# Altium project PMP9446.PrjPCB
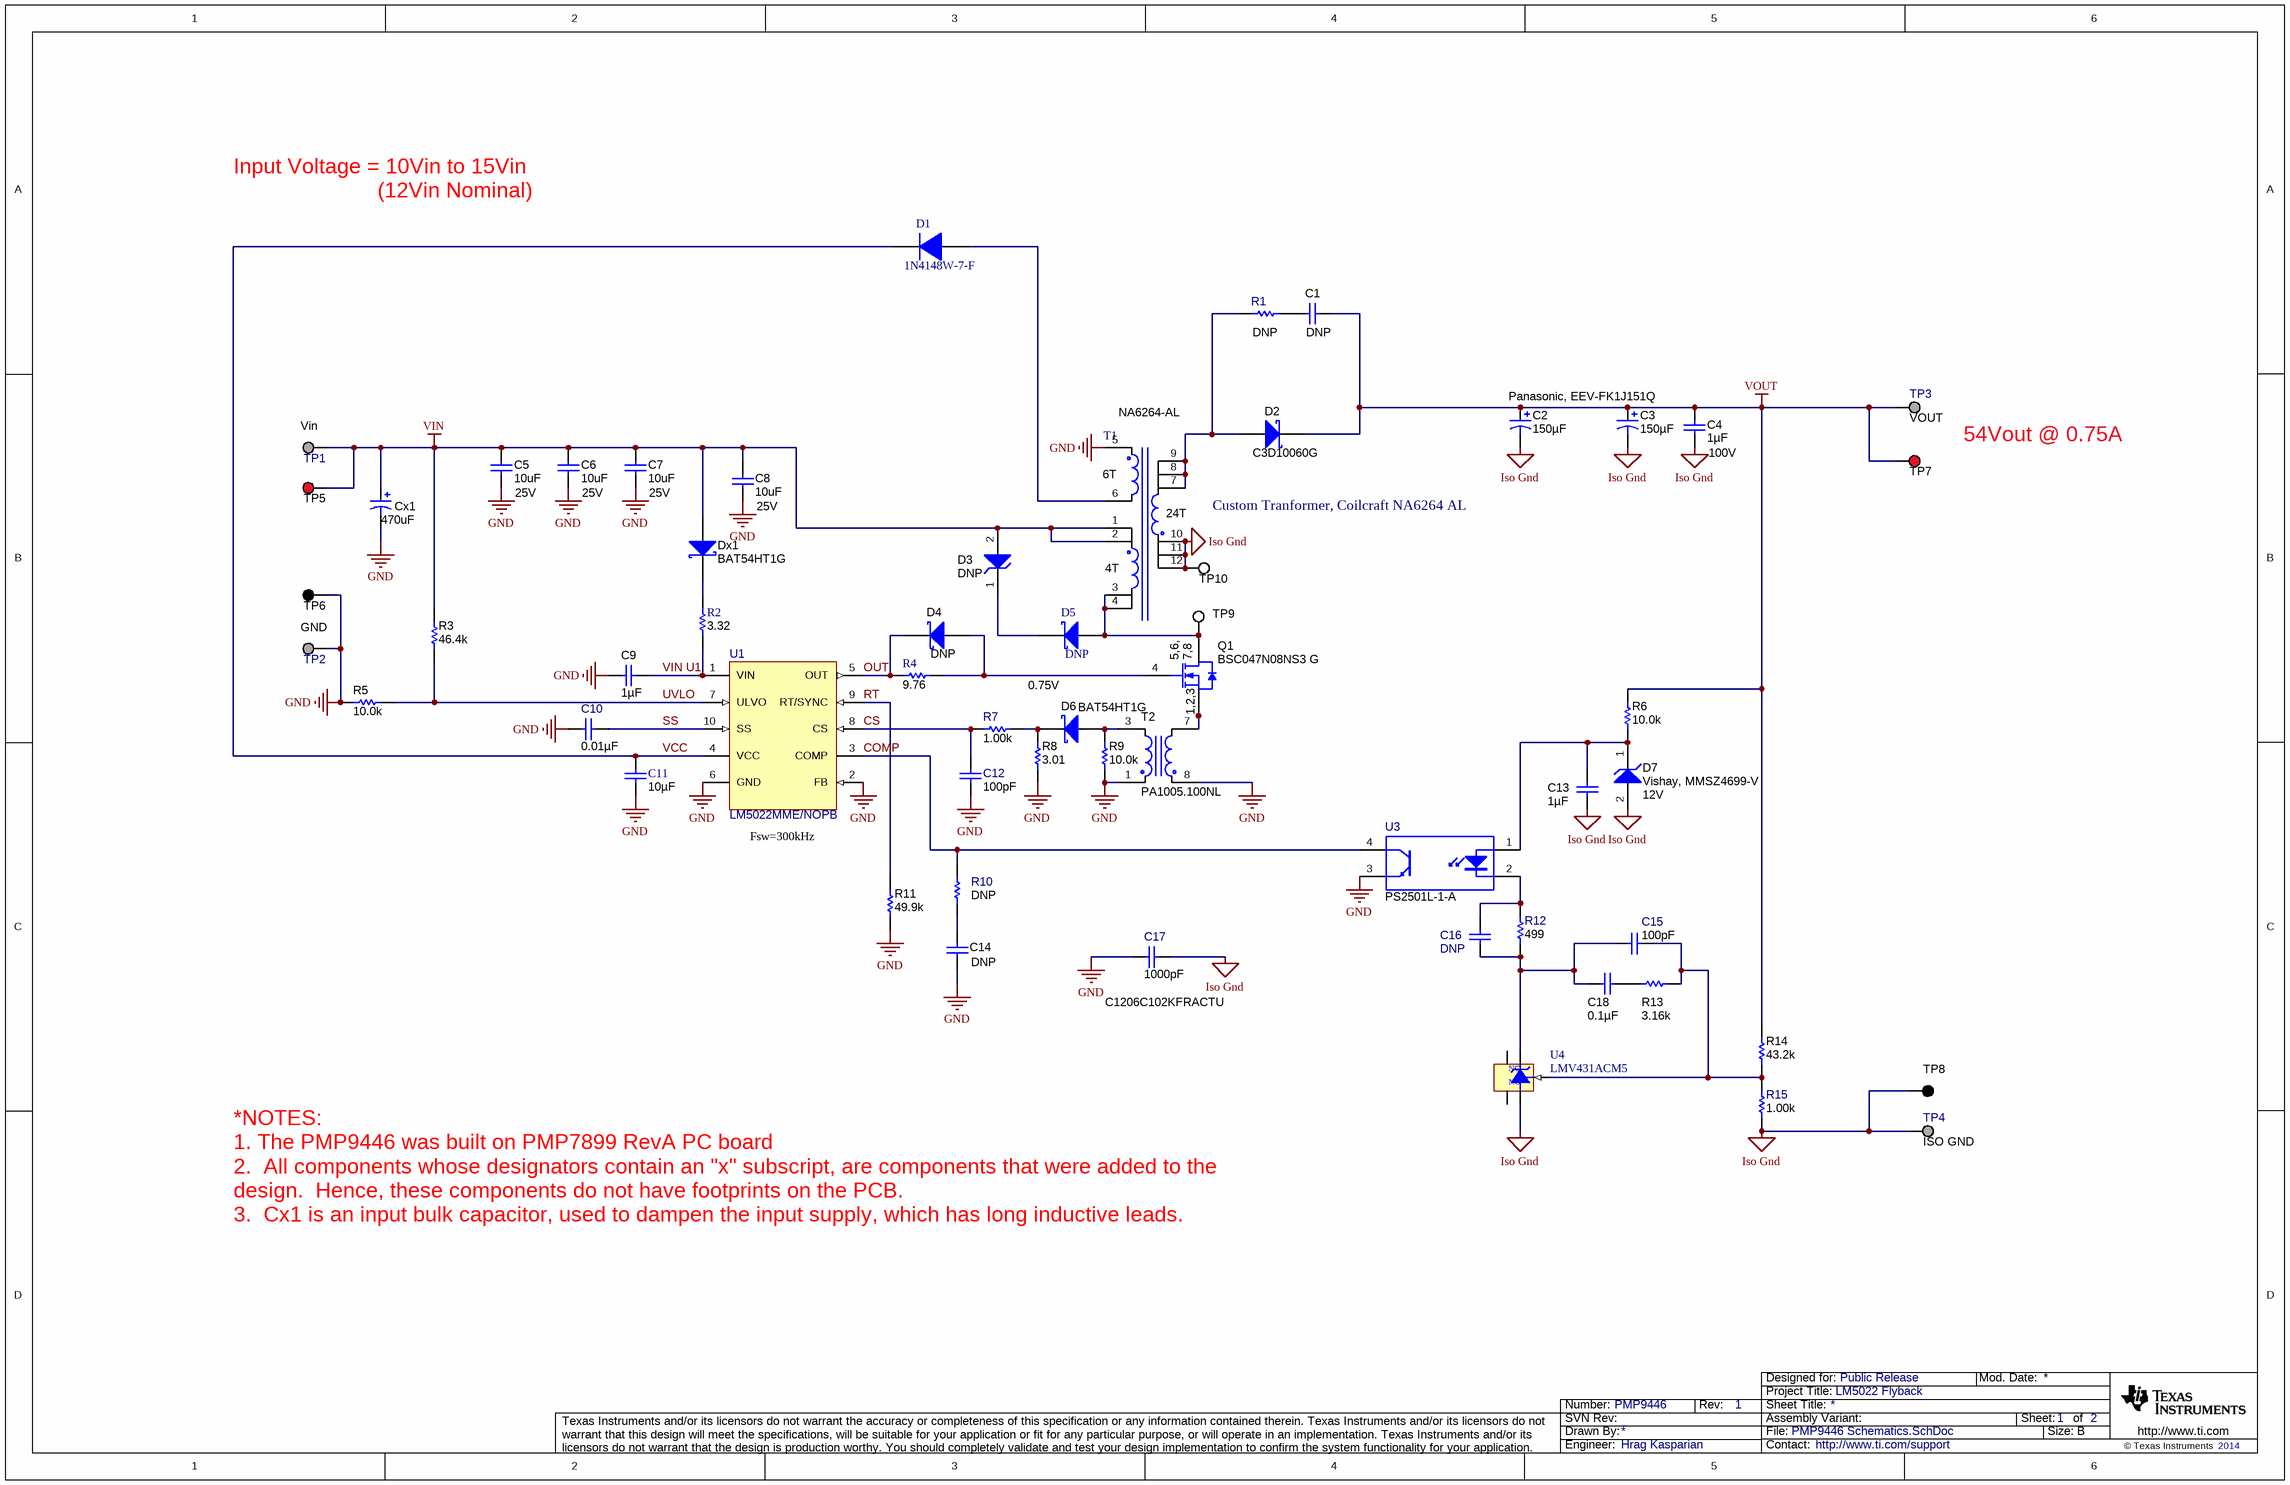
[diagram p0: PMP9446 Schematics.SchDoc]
CopyrightYear: 2014; PCB_Layout: Hrag Kasparian; PCB_Rev: 1; PRJ_Customer: Public Release; PRJ_Engineer: Hrag Kasparian; PRJ_Number: PMP9446; PRJ_Title: LM5022 Flyback; SCH_Rev: 1; TechSupport: http://www.ti.com/support
2 sheets, 67 parts. Net scope: global (net labels, ports and power ports of the same name join across sheets).
Board file: PMP7899 REVA.PcbDoc
Sheets:
  PMP9446 Schematics.SchDoc
  PMP9446_Hardware_ANSI-B.SchDoc

## Sheet PMP9446 Schematics.SchDoc
size 431 x 279 mm; DocumentNumber: 1; SheetNumber: 1; SheetTotal: 2; PageSetup: Record=PageOptions¦CenterHorizontal=True¦CenterVertical=True¦PrintScale=0.70¦XCorrection=1.00¦YCorrection=1.00¦PrintKind=1¦BorderSize=5000000¦LeftOffset=0¦BottomOffset=0¦Orientation=2¦PaperLength=1000¦PaperWidth=1000¦Scale=100¦PaperSource=15¦PrintQuality=600¦MediaType=1¦DitherType=10¦PaperKind=11x17¦PrintScaleMode=1

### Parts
C1  DNP  [0603]
C2  Panasonic, EEV-FK1J151Q  ValueDisplayed: 150µF  [SM_RADIAL_H13]
C3  ValueDisplayed: 150µF  [SM_RADIAL_H13]  (hidden comment: EEV-FK1J151Q)
C4  ValueDisplayed: 1µF  Value2: 100V  [1206]  (hidden comment: C3216X7R2A105M)
C5  10uF  VDC_V: 25V  [TBD]
C6  10uF  VDC_V: 25V  [TBD]
C7  10uF  VDC_V: 25V  [TBD]
C8  10uF  VDC_V: 25V  [TBD]
C9  ValueDisplayed: 1µF  [0805_HV]  (hidden comment: C2012X5R1E105K)
C10  ValueDisplayed: 0.01µF  [0805_HV]  (hidden comment: C2012C0G1E103J)
C11  ValueDisplayed: 10µF  [1206]  (hidden comment: GRM31CR61E106KA12L)
C12  ValueDisplayed: 100pF  [0603]  (hidden comment: C1608C0G1H101J)
C13  ValueDisplayed: 1µF  [0603]  (hidden comment: GRM188R61C105KA93D)
C14  DNP  [0603]
C15  ValueDisplayed: 100pF  [0603]  (hidden comment: C1608C0G2A101J)
C16  DNP  [0805_HV]
C17  C1206C102KFRACTU  ValueDisplayed: 1000pF  [1206]
C18  ValueDisplayed: 0.1µF  [0603]  (hidden comment: C0603C104J3RACTU)
Cx1  470uF  [TBD]
D1  1N4148W-7-F  [SOD-123]
D2  C3D10060G  [TBD]
D3  DNP  [SMB]
D4  DNP  [sod-323]
D5  DNP  value 0.75V  [SMB]
D6  BAT54HT1G  [sod-323]
D7  Vishay, MMSZ4699-V  value 12V  [SOD-123]
Dx1  BAT54HT1G  [sod-323]
Q1  BSC047N08NS3 G  [PG-TDSON-8]
R1  DNP  [1206]
R2  value 3.32  [1206]  (hidden comment: CRCW12063R32FKEA)
R3  value 46.4k  [0603]  (hidden comment: CRCW060346K4FKEA)
R4  value 9.76  [1206]  (hidden comment: CRCW12069R76FKEA)
R5  value 10.0k  [0603]  (hidden comment: CRCW060310K0FKEA)
R6  value 10.0k  [0805_HV]  (hidden comment: CRCW080510K0FKEA)
R7  value 1.00k  [0603]  (hidden comment: CRCW06031K00FKEA)
R8  value 3.01  [0603]  (hidden comment: CRCW06033R01FKEA)
R9  value 10.0k  [0603]  (hidden comment: CRCW060310K0FKEA)
R10  DNP  [0603]
R11  value 49.9k  [0603]  (hidden comment: CRCW060349K9FKEA)
R12  value 499  [0805_HV]  (hidden comment: CRCW0805499RFKEA)
R13  value 3.16k  [0603]  (hidden comment: CRCW06033K16FKEA)
R14  value 43.2k  [0603]  (hidden comment: CRCW060343K2FKEA)
R15  value 1.00k  [0603]  (hidden comment: CRCW06031K00FKEA)
T1  NA6264-AL  [NA62XX-AL]
T2  PA1005.100NL  [PA1005.XXXNL]
TP1  Vin  [Keystone1502-2]
TP2  GND  [Keystone1502-2]
TP3  VOUT  [Keystone1502-2]
TP4  ISO GND  [Keystone1502-2]
TP5  5000  [Keystone5000]  (value not drawn)
TP6  5001  [Keystone5001]  (value not drawn)
TP7  5000  [Keystone5000]  (value not drawn)
TP8  5001  [Keystone5001]  (value not drawn)
TP9  5002  [Keystone5002]  (value not drawn)
TP10  5002  [Keystone5002]  (value not drawn)
U1  LM5022MME/NOPB  [MUB10A_N]
U3  PS2501L-1-A  [PS2501L]
U4  LMV431ACM5  [MF05A_N]

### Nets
GND: C5.2 C6.2 C7.2 C8.2 C9.2 C10.2 C11.2 C12.2 C14.2 C17.2 Cx1.2(-) R5.1 R8.1 R9.1 R11.1 T1.5 T2.1 T2.8 TP2.1 TP6.1 U1.2(FB) U1.6(GND) U3.3(E)
Iso Gnd: C2.2(-) C3.2(-) C4.2 C13.2 C17.1 D7.2(A) R15.2 T1.10 T1.11 T1.12 TP4.1 TP8.1 TP10.1 U4.5(A)
VIN: C5.1 C6.1 C7.1 C8.1 Cx1.1(+) D3.2(A) Dx1.2(A) R3.2 T1.1 T1.2 TP1.1 TP5.1
VOUT: C1.1 C2.1(+) C3.1(+) C4.1 D2.1(K) R6.2 R14.2 TP3.1 TP7.1
COMP: R10.1 U1.3(COMP) U3.4(C)
CS: C12.1 R7.1 U1.8(CS)
OUT: D4.1(K) R4.2 U1.5(OUT)
RT: R11.2 U1.9(RT/SYNC)
SS: C10.1 U1.10(SS)
UVLO: R3.1 R5.2 U1.7(ULVO)
VCC: C11.1 D1.1(K) U1.4(VCC)
VIN U1: C9.1 R2.1 U1.1(VIN)
NetC1_2: C1.2 R1.1
NetC13_1: C13.1 D7.1(K) R6.1 U3.1(A)
NetC14_1: C14.1 R10.2
NetC15_1: C15.1 C16.1 C18.2 R12.2 U4.3(K)
NetC15_2: C15.2 R13.1 R14.1 R15.1 U4.4(REF)
NetC16_2: C16.2 R12.1 U3.2(K)
NetC18_1: C18.1 R13.2
NetD1_2: D1.2(A) T1.6
NetD2_2: D2.2(A) R1.2 T1.7 T1.8 T1.9
NetD3_1: D3.1(K) D5.1(K)
NetD4_2: D4.2(A) Q1.4(G) R4.1
NetD5_2: D5.2(A) Q1.5(D) Q1.6(D) Q1.7(D) Q1.8(D) Q1.9(D) T1.3 T1.4 TP9.1
NetD6_1: D6.1(K) R7.2 R8.2
NetD6_2: D6.2(A) R9.2 T2.3
NetDx1_1: Dx1.1(K) R2.2
NetQ1_1: Q1.1(S) Q1.2(S) Q1.3(S) T2.7

Not connected (* = marked no-connect by the designer): U4 1(NC) 2(NC)

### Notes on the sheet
- Input Voltage = 10Vin to 15Vin
  (12Vin Nominal)
- 54Vout @ 0.75A
- Custom Tranformer, Coilcraft NA6264 AL
- (near U1) Fsw=300kHz
- *NOTES:
  1. The PMP9446 was built on PMP7899 RevA PC board
  2.  All components whose designators contain an "x" subscript, are components that were added to the design.  Hence, these components do not have footprints on the PCB.
  3.  Cx1 is an input bulk capacitor, used to dampen the input supply, which has long inductive leads.

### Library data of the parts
C1 = C1608C0G2A101J: CAP, CERM, 100pF, 100V, +/-5%, C0G/NP0, 0603; Manufacturer: TDK; Polarized: N; CompType: Capacitor; U/M: EA; Cap_F: 0.0000000001; Tolerance_%: 5; ESR_Ohm: 0.1202; Value1: 0.1202 ohm; VDC_V: 100; TaMin_C: -55; TaMax_C: 125
C2 = EEV-FK1J151Q: CAP, AL, 150uF, 63V, +/-20%, 0.16 ohm, SMD; Polarized: Y; CompType: Capacitor; U/M: EA; Cap_F: 0.00015; Tolerance_%: 20; VDC_V: 63; ESR_Ohm: 0.16; IRMS_A: 0.8; TaMin_C: -55; TaMax_C: 105; Cap_Case: H13
C3 = EEV-FK1J151Q: CAP, AL, 150uF, 63V, +/-20%, 0.16 ohm, SMD; Manufacturer: Panasonic; Polarized: Y; CompType: Capacitor; U/M: EA; Cap_F: 0.00015; Tolerance_%: 20; VDC_V: 63; ESR_Ohm: 0.16; IRMS_A: 0.8; TaMin_C: -55; TaMax_C: 105; Cap_Case: H13
C4 = C3216X7R2A105M: CAP, CERM, 1uF, 100V, +/-20%, C Series, 1206; Manufacturer: TDK; Polarized: N; CompType: Capacitor; U/M: EA; Cap_F: 0.000001; Tolerance_%: 20; ESR_Ohm: 0.006; Value1: 0.006 ohm; VDC_V: 100; IRMS_A: 4.5; TaMin_C: -55; TaMax_C: 125
C5-C8 = Capacitor: CAP, CERM, 10uF, 25V, X7R, 20%, 1206; Manufacturer: TDK; PartNumber: C3216X7R1E106M; Polarized: N; U/M: EA
C9 = C2012X5R1E105K: CAP, CERM, 1uF, 25V, +/-10%, X5R, 0805; Manufacturer: TDK; Polarized: N; CompType: Capacitor; U/M: EA; Cap_F: 0.000001; Tolerance_%: 10; ESR_Ohm: 0.0075; Value1: 0.0075 ohm; VDC_V: 25; TaMin_C: -55; TaMax_C: 85; Cap_Case: 0805
C10 = C2012C0G1E103J: CAP, CERM, 0.01uF, 25V, +/-5%, C0G/NP0, 0805; Manufacturer: TDK; Cap_Case: 0805; ESR_Ohm: 0.03; Polarized: N; TaMax_C: 125; TaMin_C: -55; Tolerance_%: 5; VDC_V: 25; Cap_F: 0.00000001; CompType: Capacitor; Value1: 0.03 ohm; U/M: EA
C11 = GRM31CR61E106KA12L: CAP, CERM, 10uF, 25V, +/-10%, X5R, 1206; Manufacturer: MuRata; ESR_Ohm: 0.004; Polarized: N; TaMax_C: 85; TaMin_C: -55; Tolerance_%: 10; VDC_V: 25; Cap_F: 0.00001; CompType: Capacitor; U/M: EA; Value1: 0.004 ohm
C12 = C1608C0G1H101J: CAP, CERM, 100pF, 50V, +/-5%, C0G/NP0, 0603; Manufacturer: TDK; ESR_Ohm: 0.1679; Polarized: N; TaMax_C: 125; TaMin_C: -55; Tolerance_%: 5; VDC_V: 50; Cap_F: 0.0000000001; CompType: Capacitor; Value1: 0.1679 ohm; U/M: EA
C13 = GRM188R61C105KA93D: CAP, CERM, 1uF, 16V, +/-10%, X5R, 0603; Manufacturer: MuRata; Polarized: N; CompType: Capacitor; U/M: EA; Cap_F: 0.000001; Tolerance_%: 10; VDC_V: 16; TaMin_C: -55; TaMax_C: 85
C14 = C0603C104K3RACTU: CAP, CERM, 0.1uF, 25V, +/-10%, X7R, 0603; Manufacturer: Kemet; Polarized: N; CompType: Capacitor; ValueDisplayed: 0.1µF; U/M: EA; Cap_F: 0.0000001; Tolerance_%: 10; VDC_V: 25; TaMin_C: -55; TaMax_C: 125
C15 = C1608C0G2A101J: CAP, CERM, 100pF, 100V, +/-5%, C0G/NP0, 0603; Manufacturer: TDK; ESR_Ohm: 0.1202; Polarized: N; TaMax_C: 125; TaMin_C: -55; Tolerance_%: 5; VDC_V: 100; Cap_F: 0.0000000001; CompType: Capacitor; Value1: 0.1202 ohm; U/M: EA
C16 = C2012Y5V1H105Z: Capacitor; Manufacturer: TDK; Cap_Case: 0805; Polarized: N; Tolerance_%: 80; VDC_V: 50; Cap_F: 1.0E-6; Value1: Ohm; Value2: 50V; Dielectric: Y5V
C17 = C1206C102KFRACTU: CAP CER 1000PF 1.5KV X7R 1206; Manufacturer: Kemet; ESR_Ohm: 0.426; IRMS_A: 0.189; Polarized: N; TaMax_C: 125; TaMin_C: -55; Tolerance_%: 10; VDC_V: 1500; Cap_F: 0.000000001; CompType: Capacitor; Value1: 0.426 ohm; Value2: 1500V; U/M: EA
C18 = C0603C104J3RACTU: CAP, CERM, 0.1uF, 25V, +/-5%, X7R, 0603; Manufacturer: Kemet; Polarized: N; CompType: Capacitor; U/M: EA; Cap_F: 0.0000001; Tolerance_%: 5; VDC_V: 25; TaMin_C: -55; TaMax_C: 125
Cx1 = Capacitor_Polarized: CAP, Al Electrolytic, 470uF, 16V, TH; Manufacturer: SUNCON; Polarized: Y; U/M: EA
D1 = 1N4148W-7-F: Diode, Ultrafast, 100V, 0.15A, SOD-123; Manufacturer: Diodes Inc.; U/M: EA; Vf_V: 1.25; Io_A: 0.15; Vr_V: 100; TJmax_C: 150; Value: 1.25V
D2 = Diode_Schottky: Diode, SiC Schottky, 600V, 14A, D2PAK; Manufacturer: CREE; U/M: EA
D3 = 1SMB5939BT3G: Diode, Zener, 39V, 550mW, SMB; Manufacturer: ON Semiconductor; U/M: EA; Power_W: 0.55; Vz: 39; Value1: 0.55W; RJA_CperW: 226
D4 D6 Dx1 = BAT54HT1G: Diode, Schottky, 30V, 0.2A, SOD-323; Manufacturer: ON Semiconductor; Value: 0.35V; U/M: EA; Vf_V: 0.35; Io_A: 0.2; Vr_V: 30
D5 = MBRS1100T3G: Diode, Schottky, 100V, 1A, SMB; Manufacturer: ON Semiconductor; RJC_CperW: 22; Vf_V: 0.75; Io_A: 1; Vr_V: 100; TJMax_C: 150; U/M: EA
D7 = MMSZ4699-V: Diode, Zener, 12V, 500mW, SOD-123; Manufacturer: Vishay-Semiconductor; U/M: EA; Power_W: 0.5; Vz: 12; Value1: 0.5W; RJA_CperW: 67
Q1 = BSC047N08NS3 G: MOSFET, N-CH, 80V, 100A, PG-TDSON-8; Manufacturer: Infineon Technologies; Alternate Manufacturer: None; U/M: EA; ChType: N; VdsMax_V: 80; Value1: 101 ohm; Rdson45_Ohm: 101; Value2: 52 nC; QgTyp_nC: 52; Vgs_V: 20; IdsMax_A: 100
R1 = CRCW1206100RFKEA: RES, 100 ohm, 1%, 0.25W, 1206; Manufacturer: Vishay-Dale; Alternate Manufacturer: Any; Alternate PartNumber: Equivalent; CompType: Resistor; Tolerance_%: 1; VDC_V: 200; Power_W: 0.25; Res_ohm: 100; Value: 100; Value_Code: 100R; TempCo: 100 ppm/C; EIA_Code: E96; U/M: EA
R2 = CRCW12063R32FKEA: RES, 3.32 ohm, 1%, 0.25W, 1206; Manufacturer: Vishay-Dale; CompType: Resistor; Tolerance_%: 1; VDC_V: 200; Power_W: 0.25; Value_Code: 3R32; TempCo_ppm/C: 100; EIA_Code: E96; U/M: EA
R3 = CRCW060346K4FKEA: RES, 46.4k ohm, 1%, 0.1W, 0603; Manufacturer: Vishay-Dale; CompType: Resistor; Res_ohm: 46400; Value_Code: 46k4; Tolerance_%: 1; Power_W: 0.1; VDC_V: 75; TempCo: 100 ppm/C; EIA_Code: E96; U/M: EA
R4 = CRCW12069R76FKEA: RES, 9.76 ohm, 1%, 0.25W, 1206; Manufacturer: Vishay-Dale; CompType: Resistor; Tolerance_%: 1; VDC_V: 200; Power_W: 0.25; Value_Code: 9R76; EIA_Code: E96; U/M: EA; TempCo: 100 ppm/C
R5 R9 = CRCW060310K0FKEA: RES, 10.0k ohm, 1%, 0.1W, 0603; Manufacturer: Vishay-Dale; CompType: Resistor; Res_ohm: 10000; Value_Code: 10k0; Tolerance_%: 1; Power_W: 0.1; VDC_V: 75; TempCo: 100 ppm/C; EIA_Code: E96; U/M: EA
R6 = CRCW080510K0FKEA: RES, 10.0k ohm, 1%, 0.125W, 0805; Manufacturer: Vishay-Dale; CompType: Resistor; Res_ohm: 10000; Value_Code: 10k0; Tolerance_%: 1; Power_W: 0.125; VDC_V: 150; TempCo: 100 ppm/C; EIA_Code: E96; U/M: EA
R7 R10 R15 = CRCW06031K00FKEA: RES, 1.00k ohm, 1%, 0.1W, 0603; Manufacturer: Vishay-Dale; Alternate Manufacturer: Any; Alternate PartNumber: Equivalent; CompType: Resistor; Tolerance_%: 1; VDC_V: 75; Power_W: 0.1; Res_ohm: 1000; Value_Code: 1k00; TempCo: 100 ppm/C; EIA_Code: E96; U/M: EA
R8 = CRCW06033R01FKEA: RES, 3.01 ohm, 1%, 0.1W, 0603; Manufacturer: Vishay-Dale; CompType: Resistor; Value_Code: 3R01; Tolerance_%: 1; Power_W: 0.1; VDC_V: 75; TempCo: 100 ppm/C; EIA_Code: E96; U/M: EA
R11 = CRCW060349K9FKEA: RES, 49.9k ohm, 1%, 0.1W, 0603; Manufacturer: Vishay-Dale; CompType: Resistor; Res_ohm: 49900; Value_Code: 49k9; Tolerance_%: 1; Power_W: 0.1; VDC_V: 75; TempCo: 100 ppm/C; EIA_Code: E96; U/M: EA
R12 = CRCW0805499RFKEA: RES, 499 ohm, 1%, 0.125W, 0805; Manufacturer: Vishay-Dale; Alternate Manufacturer: Any; Alternate PartNumber: Equivalent; CompType: Resistor; Tolerance_%: 1; VDC_V: 150; Power_W: 0.125; Value_Code: 499R; TempCo: 100 ppm/C; EIA_Code: E96; U/M: EA
R13 = CRCW06033K16FKEA: RES, 3.16k ohm, 1%, 0.1W, 0603; Manufacturer: Vishay-Dale; CompType: Resistor; Res_ohm: 3160; Value_Code: 3k16; Tolerance_%: 1; Power_W: 0.1; VDC_V: 75; TempCo: 100 ppm/C; EIA_Code: E96; U/M: EA
R14 = CRCW060343K2FKEA: RES, 43.2k ohm, 1%, 0.1W, 0603; Manufacturer: Vishay-Dale; CompType: Resistor; Res_ohm: 43200; Value_Code: 43k2; Tolerance_%: 1; Power_W: 0.1; VDC_V: 75; TempCo: 100 ppm/C; EIA_Code: E96; U/M: EA
T1 = NA6264-AL: COILCRAFT TRANSFORMER; U/M: EA; Ns1toNp: 24;4
T2 = PA1005.100NL: SMT Current Sense Tranformer; Manufacturer: Pulse Engineering; Alternate Manufacturer: None; CompType: Transformer; Ns1toNp: 1:100; Rp: 0.75 ohm; Rs1: 5.5 ohm; SymbolCreator: a0412235; U/M: EA
TP1-TP4 = 1502-2: Terminal, Turret, TH, Double; Manufacturer: Keystone; Alternate Manufacturer: Any; Alternate PartNumber: Equivalent; CompType: Turret Terminal; U/M: EA
TP5 TP7 = 5000: Test Point, TH, Miniature, Red; Manufacturer: Keystone; Alternate Manufacturer: Any; Alternate PartNumber: Equivalent; CompType: Test Point Loop; U/M: EA
TP6 TP8 = 5001: Test Point, TH, Miniature, Black; Manufacturer: Keystone; Alternate Manufacturer: Any; Alternate PartNumber: Equivalent; CompType: Test Point Loop; U/M: EA
TP9 TP10 = 5002: Test Point, TH, Miniature, White; Manufacturer: Keystone; Alternate Manufacturer: Any; Alternate PartNumber: Equivalent; CompType: Test Point Loop; U/M: EA
U1 = LM5022MME/NOPB: 60V Low Side Controller for Boost and SEPIC, 10-pin MSOP, Pb-Free; Manufacturer: Texas Instruments; CompType: Switcher; PackageTopMarking: ZXTT*5022; PowerWise: Y
U3 = PS2501L-1-A: High Isolation Voltage Single Transistor Type OptoCoupler; Manufacturer: California Eastern Laboratories; SymbolCreator: codlsc; U/M: EA
U4 = LMV431ACM5: Low-Voltage (1.24V) Adjustable Precision Shunt Regulator, 5-pin SOT-23; Manufacturer: Texas Instruments; PackageTopMarking: N09A*XTT; PowerWise: N; CompType: MiscPower

## Sheet PMP9446_Hardware_ANSI-B.SchDoc
size 431 x 279 mm; Date: Not shown in title block; ApprovedBy: Not shown in title block; CheckedBy: Not shown in title block; Author: Not shown in title block; CompanyName: Not shown in title block; Engineer: Not shown in title block; Organization: Not shown in title block; Address1: Not shown in title block; Address2: Not shown in title block; Address3: Not shown in title block; Address4: Not shown in title block; DocumentNumber: 2; Revision: Use project parameter SCH_Rev; SheetNumber: 2; SheetTotal: 2; PageSetup: Record=PageOptions¦CenterHorizontal=True¦CenterVertical=True¦PrintScale=1.00¦XCorrection=1.00¦YCorrection=1.00¦PrintKind=0¦BorderSize=5000000¦LeftOffset=0¦BottomOffset=0¦Orientation=2¦PaperLength=1000¦PaperWidth=1000¦Scale=100¦PaperSource=15¦PrintQuality=600¦MediaType=1¦DitherType=10¦PaperKind=Letter¦PrintScaleMode=1
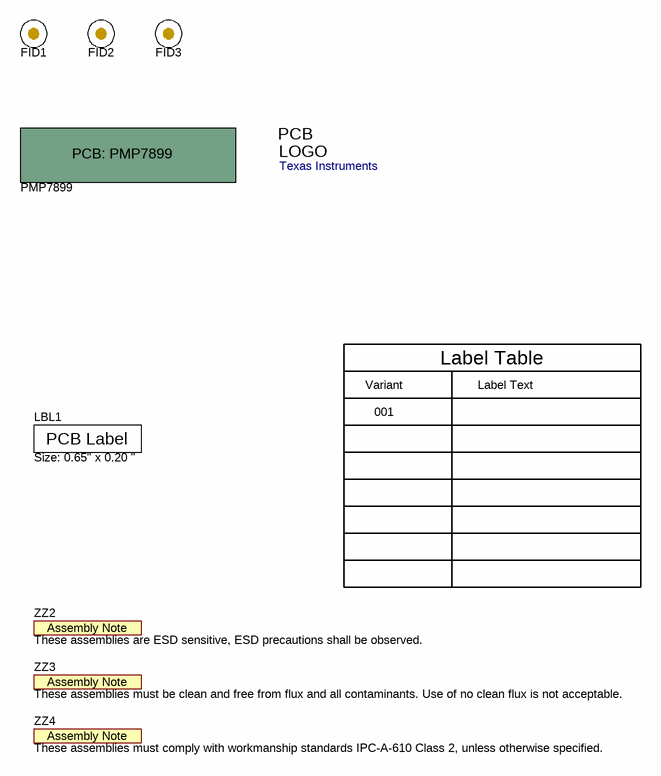
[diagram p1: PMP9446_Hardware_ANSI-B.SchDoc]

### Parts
!PCB?  PMP7899  (mechanical)
FID1  Fiducial  [Fiducial10-20]  (value not drawn)
FID2  Fiducial  [Fiducial10-20]  (value not drawn)
FID3  Fiducial  [Fiducial10-20]  (value not drawn)
LBL1  Size: 0.65" x 0.20 "  [Label_650x200]
Logo1  Texas Instruments  [TI_Stacked_SolderMask_Small]  (no BOM)
ZZ2  These assemblies are ESD sensitive, ESD precautions shall be observed.  [AssemblyNote]  (no BOM)
ZZ3  These assemblies must be clean and free from flux and all contaminants. Use of no clean flux is not acceptable.  [AssemblyNote]  (no BOM)
ZZ4  These assemblies must comply with workmanship standards IPC-A-610 Class 2, unless otherwise specified.  [AssemblyNote]  (no BOM)

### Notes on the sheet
- Variant
- Label Table
- Label Text
- 001

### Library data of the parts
!PCB? = PCB_OtherProject: Manufacturer: Any; SymbolCreator: a0412235; CompType: PCB; U/M: EA
FID1-FID3 = Fiducial: Fiducial mark.  There is nothing to buy or mount.; SymbolCreator: codlsc
LBL1 = THT-14-423-10: Thermal Transfer Printable Labels, 0.650" W x 0.200" H - 10,000 per roll; Manufacturer: Brady; SymbolCreator: a0412235; CompType: Label
Logo1 = TI_Logo: Texas Instrument Corporate Signature; SymbolCreator: a0412235
ZZ2-ZZ4 = AssemblyNote: SymbolCreator: codlsc

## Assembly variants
001: not fitted C1 C14 C16 D3 D4 D5 FID1 FID2 FID3 R1 R10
